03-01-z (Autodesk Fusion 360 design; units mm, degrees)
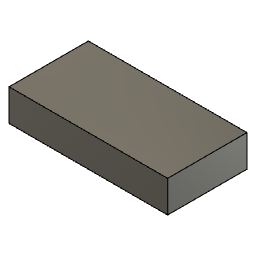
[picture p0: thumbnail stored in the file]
box_primitive "直方体プリミティブ" DistanceX 50 DistanceY 100 DistanceZ 20 OffsetDistanceX 0 OffsetDistanceY 0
